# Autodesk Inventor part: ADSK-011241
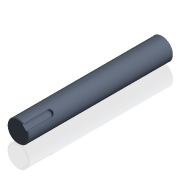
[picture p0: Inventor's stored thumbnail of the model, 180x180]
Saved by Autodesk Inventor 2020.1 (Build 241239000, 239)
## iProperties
Created: 2000-10
Part Number: ADSK-011241
Document SubType Name: Modeling
Designer: wymerj
Material: Générique
Density: 1 g/cm^3
Appearance: Métal - Plomb
Mass: 286.463 g
Surface Area: 327.764 cm^2
Volume: 286.463 cm^3
Control State: 0
Master: False
Checked Out: False
Shininess: 0.0
Length Units: 11269
Angle Units: 11279
Time Units: 11290
Mass Units: 11283
Length Display Precision: 3
Angle Display Precision: 2
Compacted: True
Dimensions: 38x38x254 mm
Mass: 0,286 kg
DocNumber: ADSK-011241.ipt
Folder: 01 - Themengebiete\Simplification\01 - Packaging machine\
VDS_Category: 3D Komponenten
Density: 0.0
Volumn: 0.0
Area: 0.0
PropertySet Name: Model Information
Author: wymerj
Revision Number: -
Title: shaft
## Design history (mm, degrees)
node "Extrusion1" dims "d1" = 254, "d2" = 0
  sketch "Sketch1"
    geometry: C1 r 19 at (0, 0); 2 further points
    constraints: 2 coincident, 1 centre point
    dimensions: "d0" = 38 diameter of C1
node "Extrusion2" dims "d3" = 47.625, "d4" = 0
  sketch "Sketch2"
    geometry: L1 (7.425, 14.496)-(14.496, 7.425); L2 (0, 0)-(13.435, 13.435); L3 (7.425, 14.496)-(9.426, 16.497); L4 (14.496, 7.425)-(16.497, 9.426); L5 (0, 0)-(19, 0); A1 r 19 centre (0, 0) between (13.435, 13.435) and (19, 0) reference; 1 further point
    constraints: 10 end point, 4 point on circle, 3 perpendicular, 1 horizontal, 1 midpoint, 1 point on line
    dimensions: "d6" = 45 deg angle of L5 L2; "d7" = 10 distance of L1.start L1.end; "d11" = 3.5 distance from line of L2.end L1
workaxis "Work Axis1"
workplane "Work Plane1"
fillet "Rundung1"
chamfer "Fase1" distance "d8" = 1; stored, may be unused: second distance "d9" = 2, angle "d10" = 45 deg
workplane "Arbeitsebene3"
node "Solide1"
node "Corps solides"
node "Corps surfaciques"
other parameters: "d5" = 0
